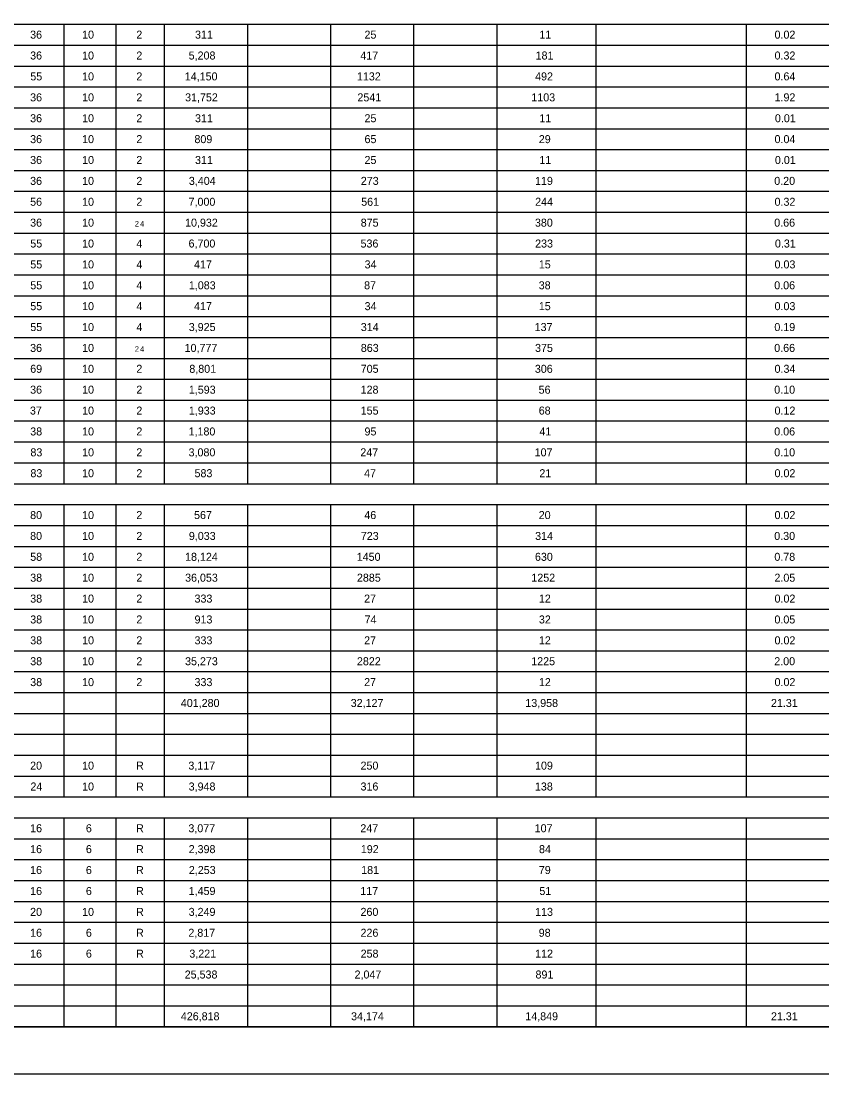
# Model space of a CAD drawing. Extents: x 0 to 34, y 0 to 22.3.
# Drawn here: x 8.49 to 16.97, y 0 to 11.14 of the extents above; entities that cross this region are included whole.
import ezdxf

# ---------------------------------------------------------------- set-up
doc = ezdxf.new("R2010")
doc.units = 0
for name, color, linetype in [('SH_Border', 7, 'Continuous'), ('SH_Cut_Line', 7, 'Continuous'), ('SH_Text', 7, 'Continuous')]:
    doc.layers.add(name, color=color, linetype=linetype)

msp = doc.modelspace()

# ---------------------------------------------------------------- linework, layer by layer
at = {"layer": 'SH_Border'}
msp.add_lwpolyline([(1.5, 21.5), (33.5, 21.5), (33.5, 0.5), (1.5, 0.5)], close=True, dxfattribs=at)
at = {"layer": 'SH_Cut_Line'}
msp.add_lwpolyline([(0, 0), (34, 0), (34, 22), (0, 22)], close=True, dxfattribs=at)
at = {"layer": 'SH_Text'}
for p, q in [((1.5, 11.111), (32, 11.111)), ((8.942, 11.111), (8.942, 6.247)), ((9.492, 11.111), (9.492, 6.247)), ((10.005, 11.111), (10.005, 6.247)), ((10.885, 11.111), (10.885, 6.247)), ((11.764, 11.111), (11.764, 6.247)), ((12.644, 11.111), (12.644, 6.247)), ((13.524, 11.111), (13.524, 6.247)), ((14.575, 11.111), (14.575, 6.247)), ((16.163, 11.111), (16.163, 6.247)), ((1.5, 10.889), (32, 10.889)), ((1.5, 10.668), (32, 10.668)), ((1.5, 10.447), (32, 10.447)), ((1.5, 10.226), (32, 10.226)), ((1.5, 10.005), (32, 10.005)), ((1.5, 9.784), (32, 9.784)), ((1.5, 9.563), (32, 9.563)), ((1.5, 9.342), (32, 9.342)), ((1.5, 9.121), (32, 9.121)), ((1.5, 8.9), (32, 8.9)), ((1.5, 8.679), (32, 8.679)), ((1.5, 8.458), (32, 8.458)), ((1.5, 8.237), (32, 8.237)), ((1.5, 8.016), (32, 8.016)), ((1.5, 7.795), (32, 7.795)), ((1.5, 7.574), (32, 7.574)), ((1.5, 7.353), (32, 7.353)), ((1.5, 7.132), (32, 7.132)), ((1.5, 6.911), (32, 6.911)), ((1.5, 6.689), (32, 6.689)), ((1.5, 6.468), (32, 6.468)), ((1.5, 6.247), (32, 6.247)), ((1.5, 6.026), (32, 6.026)), ((8.942, 6.026), (8.942, 2.932)), ((9.492, 6.026), (9.492, 2.932)), ((10.005, 6.026), (10.005, 2.932)), ((10.885, 6.026), (10.885, 2.932)), ((11.764, 6.026), (11.764, 2.932)), ((12.644, 6.026), (12.644, 2.932)), ((13.524, 6.026), (13.524, 2.932)), ((14.575, 6.026), (14.575, 2.932)), ((16.163, 6.026), (16.163, 2.932)), ((1.5, 5.805), (32, 5.805)), ((1.5, 5.584), (32, 5.584)), ((1.5, 5.363), (32, 5.363)), ((1.5, 5.142), (32, 5.142)), ((1.5, 4.921), (32, 4.921)), ((1.5, 4.7), (32, 4.7)), ((1.5, 4.479), (32, 4.479)), ((1.5, 4.258), (32, 4.258)), ((1.5, 4.037), (32, 4.037)), ((1.5, 3.816), (32, 3.816)), ((1.5, 3.595), (32, 3.595)), ((1.5, 3.374), (32, 3.374)), ((1.5, 3.153), (32, 3.153)), ((1.5, 2.932), (32, 2.932)), ((1.5, 2.711), (32, 2.711)), ((8.942, 2.711), (8.942, 0.5)), ((9.492, 2.711), (9.492, 0.5)), ((10.005, 2.711), (10.005, 0.5)), ((10.885, 2.711), (10.885, 0.5)), ((11.764, 2.711), (11.764, 0.5)), ((12.644, 2.711), (12.644, 0.5)), ((13.524, 2.711), (13.524, 0.5)), ((14.575, 2.711), (14.575, 0.5)), ((16.163, 2.711), (16.163, 0.5)), ((1.5, 2.489), (32, 2.489)), ((1.5, 2.268), (32, 2.268)), ((1.5, 2.047), (32, 2.047)), ((1.5, 1.826), (32, 1.826)), ((1.5, 1.605), (32, 1.605)), ((1.5, 1.384), (32, 1.384)), ((1.5, 1.163), (32, 1.163)), ((1.5, 0.942), (32, 0.942)), ((1.5, 0.721), (32, 0.721)), ((1.5, 0.5), (32, 0.5))]:
    msp.add_line(p, q, dxfattribs=at)

# ---------------------------------------------------------------- texts
for s, height, p in [('36', 0.0847, (8.586, 10.958)), ('10', 0.0847, (9.136, 10.958)), ('2', 0.0847, (9.71, 10.958)), ('311', 0.0847, (10.331, 10.958)), ('25', 0.0847, (12.125, 10.958)), ('11', 0.0847, (13.976, 10.958)), ('0.02', 0.0847, (16.465, 10.958)), ('36', 0.0847, (8.586, 10.737)), ('10', 0.0847, (9.136, 10.737)), ('2', 0.0847, (9.71, 10.737)), ('5,208', 0.0847, (10.264, 10.737)), ('417', 0.0847, (12.081, 10.737)), ('181', 0.0847, (13.936, 10.737)), ('0.32', 0.0847, (16.465, 10.737)), ('55', 0.0847, (8.588, 10.516)), ('10', 0.0847, (9.136, 10.516)), ('2', 0.0847, (9.71, 10.516)), ('14,150', 0.0847, (10.223, 10.516)), ('1132', 0.0847, (12.045, 10.516)), ('492', 0.0847, (13.931, 10.516)), ('0.64', 0.0847, (16.465, 10.516)), ('36', 0.0847, (8.586, 10.294)), ('10', 0.0847, (9.136, 10.294)), ('2', 0.0847, (9.71, 10.294)), ('31,752', 0.0847, (10.226, 10.294)), ('2541', 0.0847, (12.05, 10.294)), ('1103', 0.0847, (13.891, 10.294)), ('1.92', 0.0847, (16.465, 10.294)), ('36', 0.0847, (8.586, 10.073)), ('10', 0.0847, (9.136, 10.073)), ('2', 0.0847, (9.71, 10.073)), ('311', 0.0847, (10.331, 10.073)), ('25', 0.0847, (12.125, 10.073)), ('11', 0.0847, (13.976, 10.073)), ('0.01', 0.0847, (16.469, 10.073)), ('36', 0.0847, (8.586, 9.852)), ('10', 0.0847, (9.136, 9.852)), ('2', 0.0847, (9.71, 9.852)), ('809', 0.0847, (10.325, 9.852)), ('65', 0.0847, (12.125, 9.852)), ('29', 0.0847, (13.97, 9.852)), ('0.04', 0.0847, (16.465, 9.852)), ('36', 0.0847, (8.586, 9.631)), ('10', 0.0847, (9.136, 9.631)), ('2', 0.0847, (9.71, 9.631)), ('311', 0.0847, (10.331, 9.631)), ('25', 0.0847, (12.125, 9.631)), ('11', 0.0847, (13.976, 9.631)), ('0.01', 0.0847, (16.469, 9.631)), ('36', 0.0847, (8.586, 9.41)), ('10', 0.0847, (9.136, 9.41)), ('2', 0.0847, (9.71, 9.41)), ('3,404', 0.0847, (10.266, 9.41)), ('273', 0.0847, (12.086, 9.41)), ('119', 0.0847, (13.93, 9.41)), ('0.20', 0.0847, (16.462, 9.41)), ('56', 0.0847, (8.586, 9.189)), ('10', 0.0847, (9.136, 9.189)), ('2', 0.0847, (9.71, 9.189)), ('7,000', 0.0847, (10.263, 9.189)), ('561', 0.0847, (12.09, 9.189)), ('244', 0.0847, (13.931, 9.189)), ('0.32', 0.0847, (16.465, 9.189)), ('36', 0.0847, (8.586, 8.968)), ('10', 0.0847, (9.136, 8.968)), ('2', 0.0593, (9.694, 8.969)), ('4', 0.0593, (9.75, 8.969)), ('10,932', 0.0847, (10.226, 8.968)), ('875', 0.0847, (12.085, 8.968)), ('380', 0.0847, (13.929, 8.968)), ('0.66', 0.0847, (16.462, 8.968)), ('55', 0.0847, (8.588, 8.747)), ('10', 0.0847, (9.136, 8.747)), ('4', 0.0847, (9.711, 8.747)), ('6,700', 0.0847, (10.263, 8.747)), ('536', 0.0847, (12.083, 8.747)), ('233', 0.0847, (13.931, 8.747)), ('0.31', 0.0847, (16.469, 8.747)), ('55', 0.0847, (8.588, 8.526)), ('10', 0.0847, (9.136, 8.526)), ('4', 0.0847, (9.711, 8.526)), ('417', 0.0847, (10.321, 8.526)), ('34', 0.0847, (12.126, 8.526)), ('15', 0.0847, (13.97, 8.526)), ('0.03', 0.0847, (16.465, 8.526)), ('55', 0.0847, (8.588, 8.305)), ('10', 0.0847, (9.136, 8.305)), ('4', 0.0847, (9.711, 8.305)), ('1,083', 0.0847, (10.266, 8.305)), ('87', 0.0847, (12.121, 8.305)), ('38', 0.0847, (13.969, 8.305)), ('0.06', 0.0847, (16.462, 8.305)), ('55', 0.0847, (8.588, 8.084)), ('10', 0.0847, (9.136, 8.084)), ('4', 0.0847, (9.711, 8.084)), ('417', 0.0847, (10.321, 8.084)), ('34', 0.0847, (12.126, 8.084)), ('15', 0.0847, (13.97, 8.084)), ('0.03', 0.0847, (16.465, 8.084)), ('55', 0.0847, (8.588, 7.863)), ('10', 0.0847, (9.136, 7.863)), ('4', 0.0847, (9.711, 7.863)), ('3,925', 0.0847, (10.265, 7.863)), ('314', 0.0847, (12.086, 7.863)), ('137', 0.0847, (13.926, 7.863)), ('0.19', 0.0847, (16.463, 7.863)), ('36', 0.0847, (8.586, 7.642)), ('10', 0.0847, (9.136, 7.642)), ('2', 0.0593, (9.694, 7.643)), ('4', 0.0593, (9.75, 7.643)), ('10,777', 0.0847, (10.221, 7.642)), ('863', 0.0847, (12.086, 7.642)), ('375', 0.0847, (13.93, 7.642)), ('0.66', 0.0847, (16.462, 7.642)), ('69', 0.0847, (8.587, 7.421)), ('10', 0.0847, (9.136, 7.421)), ('2', 0.0847, (9.71, 7.421)), ('8,801', 0.0847, (10.271, 7.421)), ('705', 0.0847, (12.085, 7.421)), ('306', 0.0847, (13.928, 7.421)), ('0.34', 0.0847, (16.465, 7.421)), ('36', 0.0847, (8.586, 7.2)), ('10', 0.0847, (9.136, 7.2)), ('2', 0.0847, (9.71, 7.2)), ('1,593', 0.0847, (10.266, 7.2)), ('128', 0.0847, (12.084, 7.2)), ('56', 0.0847, (13.968, 7.2)), ('0.10', 0.0847, (16.462, 7.2)), ('37', 0.0847, (8.584, 6.979)), ('10', 0.0847, (9.136, 6.979)), ('2', 0.0847, (9.71, 6.979)), ('1,933', 0.0847, (10.266, 6.979)), ('155', 0.0847, (12.085, 6.979)), ('68', 0.0847, (13.969, 6.979)), ('0.12', 0.0847, (16.465, 6.979)), ('38', 0.0847, (8.587, 6.758)), ('10', 0.0847, (9.136, 6.758)), ('2', 0.0847, (9.71, 6.758)), ('1,180', 0.0847, (10.263, 6.758)), ('95', 0.0847, (12.125, 6.758)), ('41', 0.0847, (13.976, 6.758)), ('0.06', 0.0847, (16.462, 6.758)), ('83', 0.0847, (8.589, 6.537)), ('10', 0.0847, (9.136, 6.537)), ('2', 0.0847, (9.71, 6.537)), ('3,080', 0.0847, (10.263, 6.537)), ('247', 0.0847, (12.081, 6.537)), ('107', 0.0847, (13.926, 6.537)), ('0.10', 0.0847, (16.462, 6.537)), ('83', 0.0847, (8.589, 6.316)), ('10', 0.0847, (9.136, 6.316)), ('2', 0.0847, (9.71, 6.316)), ('583', 0.0847, (10.326, 6.316)), ('47', 0.0847, (12.121, 6.316)), ('21', 0.0847, (13.976, 6.316)), ('0.02', 0.0847, (16.465, 6.316)), ('80', 0.0847, (8.586, 5.873)), ('10', 0.0847, (9.136, 5.873)), ('2', 0.0847, (9.71, 5.873)), ('567', 0.0847, (10.321, 5.873)), ('46', 0.0847, (12.123, 5.873)), ('20', 0.0847, (13.969, 5.873)), ('0.02', 0.0847, (16.465, 5.873)), ('80', 0.0847, (8.586, 5.652)), ('10', 0.0847, (9.136, 5.652)), ('2', 0.0847, (9.71, 5.652)), ('9,033', 0.0847, (10.266, 5.652)), ('723', 0.0847, (12.086, 5.652)), ('314', 0.0847, (13.931, 5.652)), ('0.30', 0.0847, (16.462, 5.652)), ('58', 0.0847, (8.587, 5.431)), ('10', 0.0847, (9.136, 5.431)), ('2', 0.0847, (9.71, 5.431)), ('18,124', 0.0847, (10.226, 5.431)), ('1450', 0.0847, (12.043, 5.431)), ('630', 0.0847, (13.929, 5.431)), ('0.78', 0.0847, (16.463, 5.431)), ('38', 0.0847, (8.587, 5.21)), ('10', 0.0847, (9.136, 5.21)), ('2', 0.0847, (9.71, 5.21)), ('36,053', 0.0847, (10.226, 5.21)), ('2885', 0.0847, (12.045, 5.21)), ('1252', 0.0847, (13.891, 5.21)), ('2.05', 0.0847, (16.464, 5.21)), ('38', 0.0847, (8.587, 4.989)), ('10', 0.0847, (9.136, 4.989)), ('2', 0.0847, (9.71, 4.989)), ('333', 0.0847, (10.326, 4.989)), ('27', 0.0847, (12.121, 4.989)), ('12', 0.0847, (13.971, 4.989)), ('0.02', 0.0847, (16.465, 4.989)), ('38', 0.0847, (8.587, 4.768)), ('10', 0.0847, (9.136, 4.768)), ('2', 0.0847, (9.71, 4.768)), ('913', 0.0847, (10.326, 4.768)), ('74', 0.0847, (12.126, 4.768)), ('32', 0.0847, (13.971, 4.768)), ('0.05', 0.0847, (16.464, 4.768)), ('38', 0.0847, (8.587, 4.547)), ('10', 0.0847, (9.136, 4.547)), ('2', 0.0847, (9.71, 4.547)), ('333', 0.0847, (10.326, 4.547)), ('27', 0.0847, (12.121, 4.547)), ('12', 0.0847, (13.971, 4.547)), ('0.02', 0.0847, (16.465, 4.547)), ('38', 0.0847, (8.587, 4.326)), ('10', 0.0847, (9.136, 4.326)), ('2', 0.0847, (9.71, 4.326)), ('35,273', 0.0847, (10.226, 4.326)), ('2822', 0.0847, (12.045, 4.326)), ('1225', 0.0847, (13.89, 4.326)), ('2.00', 0.0847, (16.462, 4.326)), ('38', 0.0847, (8.587, 4.105)), ('10', 0.0847, (9.136, 4.105)), ('2', 0.0847, (9.71, 4.105)), ('333', 0.0847, (10.326, 4.105)), ('27', 0.0847, (12.121, 4.105)), ('12', 0.0847, (13.971, 4.105)), ('0.02', 0.0847, (16.465, 4.105)), ('401,280', 0.0847, (10.181, 3.884)), ('32,127', 0.0847, (11.979, 3.884)), ('13,958', 0.0847, (13.827, 3.884)), ('21.31', 0.0847, (16.427, 3.884)), ('20', 0.0847, (8.586, 3.221)), ('10', 0.0847, (9.136, 3.221)), ('R', 0.0847, (9.707, 3.221)), ('3,117', 0.0847, (10.261, 3.221)), ('250', 0.0847, (12.083, 3.221)), ('109', 0.0847, (13.93, 3.221)), ('24', 0.0847, (8.589, 3)), ('10', 0.0847, (9.136, 3)), ('R', 0.0847, (9.707, 3)), ('3,948', 0.0847, (10.264, 3)), ('316', 0.0847, (12.083, 3)), ('138', 0.0847, (13.929, 3)), ('16', 0.0847, (8.586, 2.558)), ('6', 0.0847, (9.176, 2.558)), ('R', 0.0847, (9.707, 2.558)), ('3,077', 0.0847, (10.261, 2.558)), ('247', 0.0847, (12.081, 2.558)), ('107', 0.0847, (13.926, 2.558)), ('16', 0.0847, (8.586, 2.337)), ('6', 0.0847, (9.176, 2.337)), ('R', 0.0847, (9.707, 2.337)), ('2,398', 0.0847, (10.264, 2.337)), ('192', 0.0847, (12.086, 2.337)), ('84', 0.0847, (13.972, 2.337)), ('16', 0.0847, (8.586, 2.116)), ('6', 0.0847, (9.176, 2.116)), ('R', 0.0847, (9.707, 2.116)), ('2,253', 0.0847, (10.266, 2.116)), ('181', 0.0847, (12.09, 2.116)), ('79', 0.0847, (13.97, 2.116)), ('16', 0.0847, (8.586, 1.894)), ('6', 0.0847, (9.176, 1.894)), ('R', 0.0847, (9.707, 1.894)), ('1,459', 0.0847, (10.264, 1.894)), ('117', 0.0847, (12.081, 1.894)), ('51', 0.0847, (13.976, 1.894)), ('20', 0.0847, (8.586, 1.673)), ('10', 0.0847, (9.136, 1.673)), ('R', 0.0847, (9.707, 1.673)), ('3,249', 0.0847, (10.264, 1.673)), ('260', 0.0847, (12.083, 1.673)), ('113', 0.0847, (13.931, 1.673)), ('16', 0.0847, (8.586, 1.452)), ('6', 0.0847, (9.176, 1.452)), ('R', 0.0847, (9.707, 1.452)), ('2,817', 0.0847, (10.261, 1.452)), ('226', 0.0847, (12.083, 1.452)), ('98', 0.0847, (13.969, 1.452)), ('16', 0.0847, (8.586, 1.231)), ('6', 0.0847, (9.176, 1.231)), ('R', 0.0847, (9.707, 1.231)), ('3,221', 0.0847, (10.271, 1.231)), ('258', 0.0847, (12.084, 1.231)), ('112', 0.0847, (13.931, 1.231)), ('25,538', 0.0847, (10.222, 1.01)), ('2,047', 0.0847, (12.02, 1.01)), ('891', 0.0847, (13.935, 1.01)), ('426,818', 0.0847, (10.181, 0.568)), ('34,174', 0.0847, (11.983, 0.568)), ('14,849', 0.0847, (13.827, 0.568)), ('21.31', 0.0847, (16.427, 0.568))]:
    msp.add_text(s, height=height, dxfattribs=at).set_placement(p)

doc.saveas('drawing.dxf')
